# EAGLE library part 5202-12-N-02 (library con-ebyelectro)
Barrier Blocks Sreies 5202 Source: http://www.ebyelectro.com/PDF/5202-XX-N-02.pdf
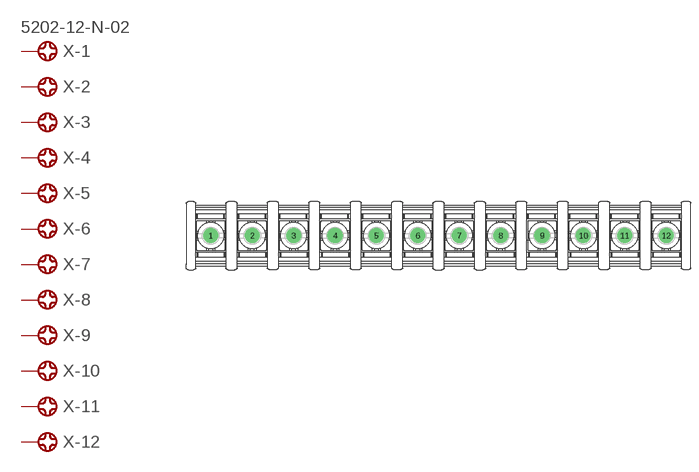
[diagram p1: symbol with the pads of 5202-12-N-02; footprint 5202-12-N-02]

Designator prefix X; gates -1=CONNECT-VALUE -2=CONNECT -3=CONNECT -4=CONNECT -5=CONNECT -6=CONNECT -7=CONNECT -8=CONNECT -9=CONNECT -10=CONNECT -11=CONNECT -12=CONNECT

## 5202-12-N-02 (OC_FARNELL: unknown; OC_NEWARK: unknown)  [5202-12-N-02]
1  -1:1  pas
2  -2:1  pas
3  -3:1  pas
4  -4:1  pas
5  -5:1  pas
6  -6:1  pas
7  -7:1  pas
8  -8:1  pas
9  -9:1  pas
10  -10:1  pas
11  -11:1  pas
12  -12:1  pas

## Footprint 5202-12-N-02 (pad centres in mm)
Barrier Blocks Sreies 5202 Source: http://www.ebyelectro.com/PDF/5202-XX-N-02.pdf
drill 1.5 pad 3 round: 1 -45.375,0; 2 -37.125,0; 3 -28.875,0; 4 -20.625,0; 5 -12.375,0; 6 -4.125,0; 7 4.125,0; 8 12.375,0; 9 20.625,0; 10 28.875,0; 11 37.125,0; 12 45.375,0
